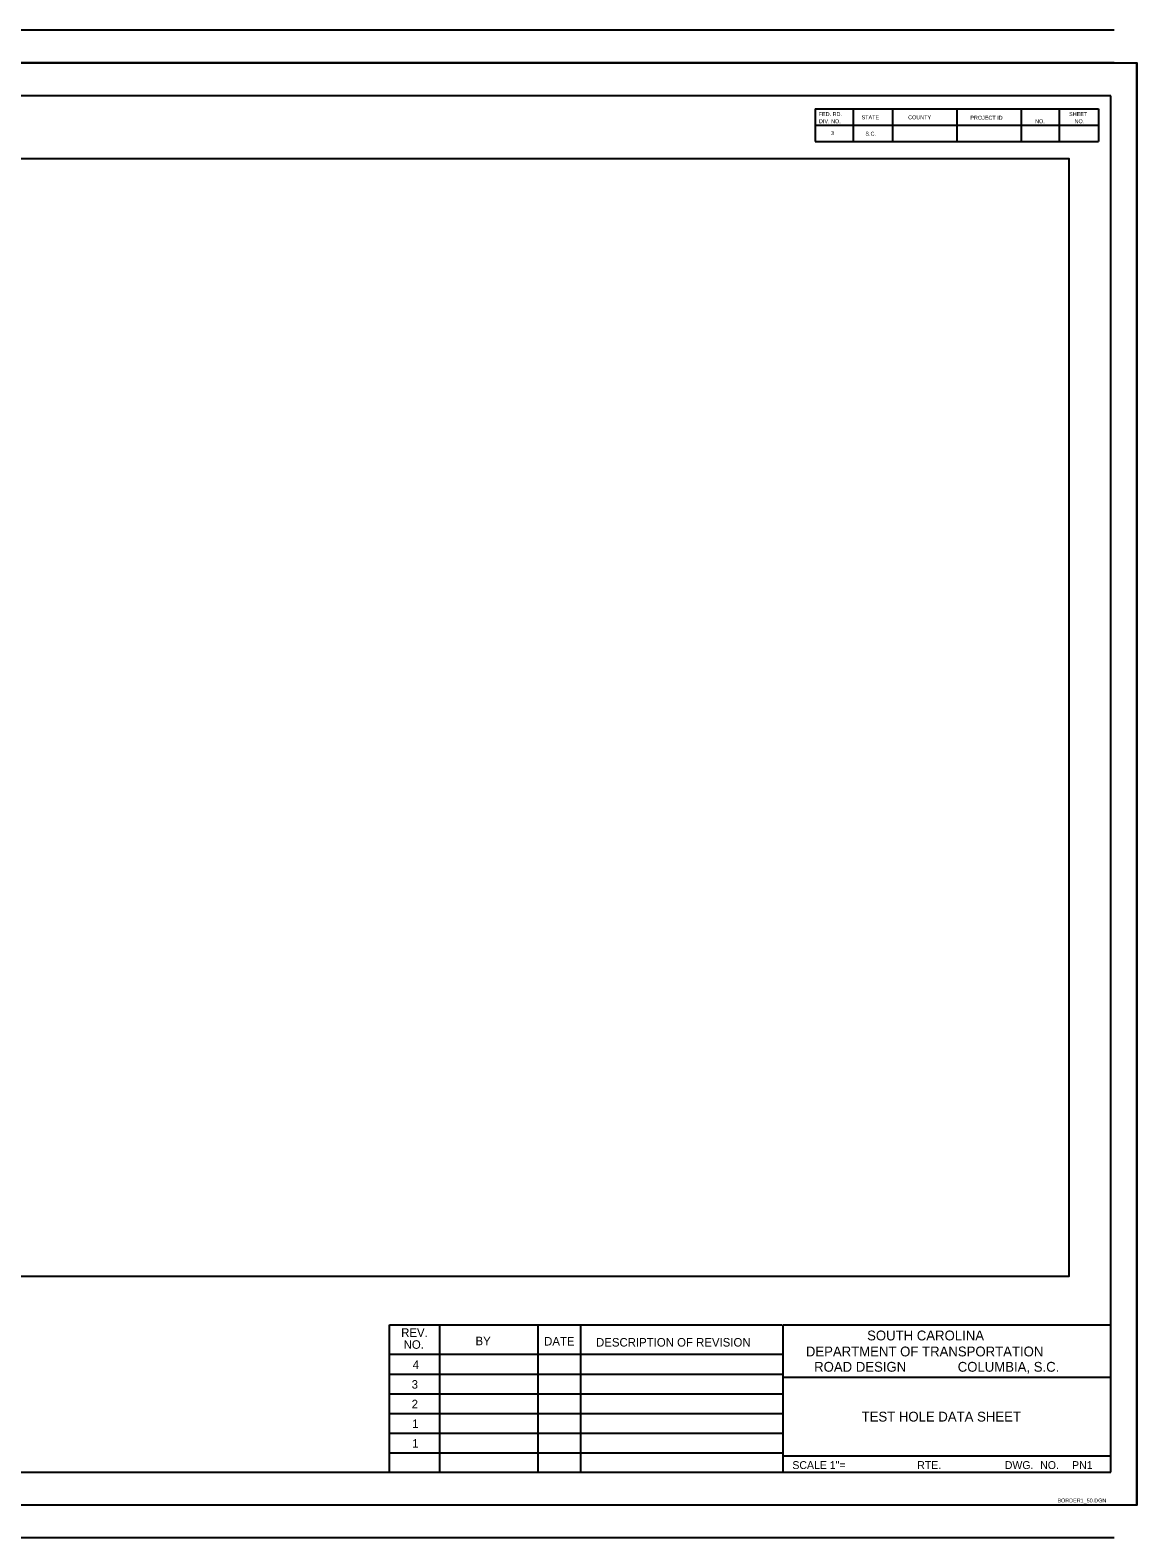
# Model space of a CAD drawing. Extents: x 12327 to 14123, y 15818 to 16968.
# Drawn here: x 13279 to 14123, y 15818 to 16968 of the extents above; entities that cross this region are included whole.
import ezdxf

# ---------------------------------------------------------------- set-up
doc = ezdxf.new("R2010")
doc.units = 0
for name, color, linetype in [('GN_Transparent 20', 7, 'Continuous'), ('RD_SHT_Bndy', 7, 'Continuous'), ('RD_SHT_Iplotshp', 7, 'Continuous'), ('RD_SHT_Snap', 7, 'Continuous'), ('RD_SHT_TX', 7, 'Continuous')]:
    doc.layers.add(name, color=color, linetype=linetype)

msp = doc.modelspace()

# ---------------------------------------------------------------- linework, layer by layer
at = {"layer": 'GN_Transparent 20'}
msp.add_lwpolyline([(12457.7, 16018), (14071.7, 16018), (14071.7, 16870.3), (12457.7, 16870.3)], close=True, dxfattribs=at)
at = {"layer": 'RD_SHT_Bndy'}
for p, q in [((14105.9, 16968.4), (12345.9, 16968.4)), ((14105.9, 16943.4), (12345.9, 16943.4)), ((14103.5, 16918.4), (12428.5, 16918.4)), ((14103.5, 15868.4), (14103.5, 16918.4)), ((13878, 16908.4), (13878, 16883.4)), ((13878, 16908.4), (14035, 16908.4)), ((13907, 16908.4), (13907, 16883.4)), ((13937, 16908.4), (13937, 16883.4)), ((13986, 16908.4), (13986, 16883.4)), ((14035, 16908.4), (14035, 16883.4)), ((14035, 16908.4), (14094, 16908.4)), ((14064, 16908.4), (14064, 16883.4)), ((14094, 16908.4), (14094, 16883.4)), ((13878, 16895.9), (14035, 16895.9)), ((14035, 16895.9), (14094, 16895.9)), ((13878, 16883.4), (14035, 16883.4)), ((14035, 16883.4), (14094, 16883.4)), ((13553.3, 15868.4), (13553.3, 15980.9)), ((13553.3, 15980.9), (13852.7, 15980.9)), ((13591.8, 15868.4), (13591.8, 15980.9)), ((13666.8, 15868.4), (13666.8, 15980.9)), ((13699.3, 15868.4), (13699.3, 15980.9)), ((13853.5, 15980.9), (14103.5, 15980.9)), ((13853.5, 15868.2), (13853.5, 15980.9)), ((13554.1, 15958.4), (13853.5, 15958.4)), ((13554.1, 15943.2), (13853.5, 15943.2)), ((13853.5, 15940.9), (14103.5, 15940.9)), ((13554.1, 15928.2), (13853.5, 15928.2)), ((13554.1, 15913.2), (13853.5, 15913.2)), ((13554.1, 15898.2), (13853.5, 15898.2)), ((13554.1, 15883.2), (13853.5, 15883.2)), ((13853.5, 15880.9), (14103.5, 15880.9)), ((12428.5, 15868.4), (14103.5, 15868.4)), ((14105.9, 15843.4), (12345.9, 15843.4)), ((14105.9, 15818.4), (12345.9, 15818.4))]:
    msp.add_line(p, q, dxfattribs=at)
at = {"layer": 'RD_SHT_Iplotshp'}
msp.add_lwpolyline([(12327.3, 16943.4), (14123.3, 16943.4), (14123.3, 15843.4), (12327.3, 15843.4)], close=True, dxfattribs=at)
at = {"layer": 'RD_SHT_Snap'}
msp.add_line((14123.3, 15843.4), (14123.3, 16943.4), dxfattribs=at)

# ---------------------------------------------------------------- texts
at = {"layer": 'RD_SHT_TX'}
for s, height, p in [('FED. RD.', 3, (13880.7, 16902.9)), ('SHEET', 3, (14071.6, 16902.9)), ('DIV. NO.', 3, (13880.9, 16897.4)), ('STATE', 3, (13913.4, 16900.4)), ('COUNTY', 3, (13948.9, 16900.4)), ('PROJECT ID', 3, (13996.3, 16900.1)), ('NO.', 3, (14045.7, 16897.4)), ('NO.', 3, (14075.8, 16897.4)), ('3', 3, (13890, 16888.4)), ('S.C.', 3, (13916.3, 16887.9)), ('REV.', 6.5, (13562.3, 15971.7)), ('SOUTH CAROLINA', 7.5, (13917.6, 15969)), ('NO.', 6.5, (13564.2, 15962.6)), ('BY', 6.5, (13619, 15965.3)), ('DATE', 6.5, (13671.3, 15965.1)), ('DESCRIPTION OF REVISION', 6.5, (13710.9, 15964.3)), ('DEPARTMENT OF TRANSPORTATION', 7.5, (13870.9, 15956.8)), ('4', 6.5, (13571.1, 15947.2)), ('ROAD DESIGN', 7.5, (13877.2, 15945.1)), ('COLUMBIA, S.C.', 7.5, (13986.7, 15945.1)), ('3', 6.5, (13570.3, 15932.2)), ('2', 6.5, (13570.3, 15917.2)), ('1', 6.5, (13570.7, 15902.2)), ('TEST HOLE DATA SHEET', 7.5, (13913.4, 15907.1)), ('1', 6.5, (13570.7, 15887.2)), ('SCALE 1"=', 6, (13860.6, 15870.9)), ('RTE.', 6, (13955.8, 15870.9)), ('DWG.', 6, (14022.6, 15870.9)), ('NO.', 6, (14049.6, 15870.9)), ('PN1', 6, (14073.9, 15870.9)), ('BORDER1_50.DGN', 3, (14062.7, 15845.4))]:
    msp.add_text(s, height=height, dxfattribs=at).set_placement(p)

doc.saveas('drawing.dxf')
